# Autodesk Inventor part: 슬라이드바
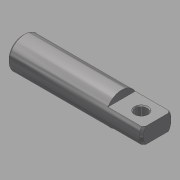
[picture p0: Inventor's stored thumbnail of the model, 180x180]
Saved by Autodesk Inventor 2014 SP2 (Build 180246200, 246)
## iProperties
Created: 2015-12
Part Number: 슬라이드바
Material: 스테인리스강
Document SubType Name: Modeling
Designer: mduedu
Density: 8.08 g/cm^3
Appearance: 반광택
Author: mduedu
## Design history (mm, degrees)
sketch "스케치1"
  geometry: L1 (-34, 0)-(34, 0); L2 (-34, 0)-(-34, 8); L3 (-34, 8)-(34, 8); L4 (34, 8)-(34, 0); 2 further points
  constraints: 8 end point, 2 perpendicular, 1 coincident, 1 horizontal, 1 midpoint, 1 vertical
  dimensions: "d0" = 68 distance of L2.end L3.end; "d2" = 16 diameter of L3 L1
revolve "회전1" sketch "스케치1" stored, may be unused: angle "d3" = 90 deg
sketch "스케치2"
  geometry: L1 (34, -8)-(34, 8) reference; L2 (0, 0)-(34, 0); L3 (34, 4)-(16, 4); L4 (16, 4)-(16, 8); L5 (16, 8)-(34, 8); L6 (34, 8)-(34, 4); L7 (-34, 8)-(34, 8) reference
  constraints: 10 end point, 2 parallel, 1 collinear, 1 horizontal, 1 midpoint, 1 perpendicular, 1 point on line
  dimensions: "d4" = 18 distance of L4.end L5.end; "d6" = 4 distance between parallel lines of L3 L2
extrude "돌출1" cut sketch "스케치2" stored distance "d8" = 10; taper "d9" = 0 deg
sketch "스케치3"
  geometry: L1 (0, 0)-(0, -13.856) reference; 2 further points
  constraints: 1 horizontal alignment
  dimensions: "d10" = 10 distance from line of point (10, -6.928) L1
hole "구멍1" sketch "스케치3" at (10, -6.928) diameter "d11" = 6; stored, may be unused: countersink angle "d15" = 90 deg, drill point angle "d17" = 118 deg; dims "d12" = 6, "d13" = 4, "d14" = 2, "d16" = 8
chamfer "모따기1" distance "d18" = 0.5; stored, may be unused: second distance "d19" = 2, angle "d20" = 45 deg
chamfer "모따기2" distance "d21" = 1; stored, may be unused: second distance "d22" = 2, angle "d23" = 45 deg
hole "구멍2" diameter "d26" = 4.917; stored, may be unused: countersink angle "d30" = 90 deg, drill point angle "d32" = 118 deg; dims "d24" = 10, "d25" = 10, "d27" = 12, "d28" = 4, "d29" = 2, "d31" = 13
chamfer "모따기3" distance "d33" = 1; stored, may be unused: second distance "d34" = 2, angle "d35" = 45 deg
node "솔리드1"
mirror "대칭1"
